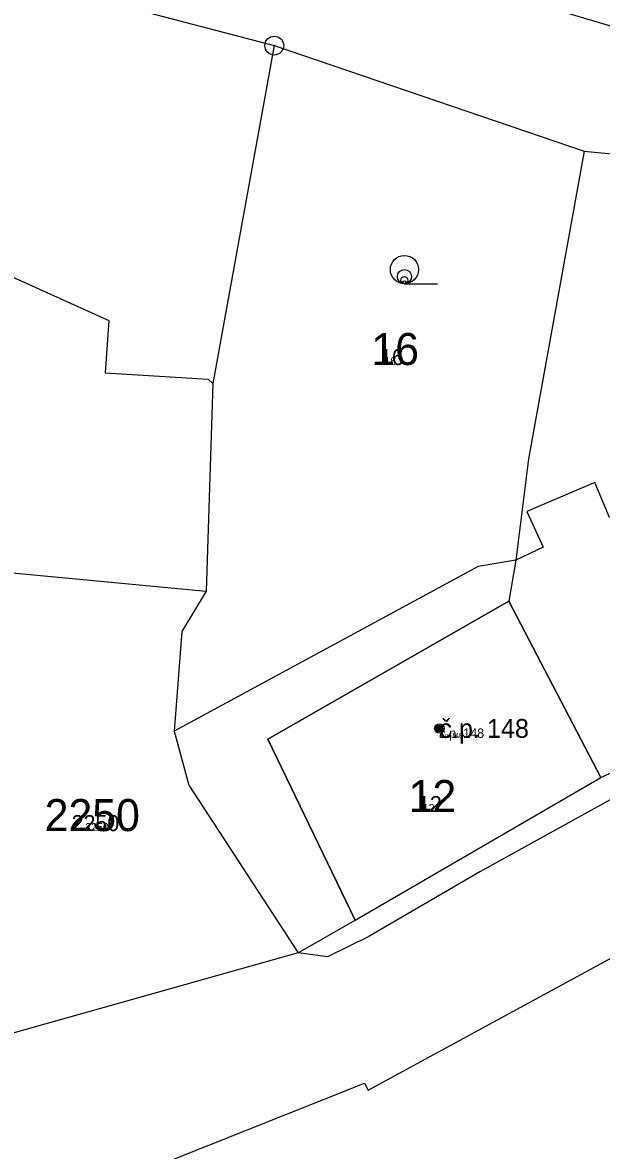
# Model space of a CAD drawing. Extents: x -744652 to -739090, y -980828 to -975855.
# Drawn here: x -742346.1 to -742315.3, y -978625.3 to -978565.5 of the extents above; entities that cross this region are included whole.
import ezdxf

# ---------------------------------------------------------------- set-up
doc = ezdxf.new("R2010")
doc.units = 0
for name, color, linetype in [('KAT_02_hranice parcel', 7, 'Continuous'), ('KAT_03_1000_st čísla parcelní', 7, 'Continuous'), ('KAT_03_1000_čísla parcelní', 7, 'Continuous'), ('KAT_03_1000_čísla popisná', 7, 'Continuous'), ('KAT_03_100_st čísla parcelní', 7, 'Continuous'), ('KAT_03_100_čísla parcelní', 7, 'Continuous'), ('KAT_03_100_čísla popisná', 7, 'Continuous'), ('KAT_03_250_st čísla parcelní', 7, 'Continuous'), ('KAT_03_250_čísla parcelní', 7, 'Continuous'), ('KAT_03_250_čísla popisná', 7, 'Continuous'), ('KAT_03_500_st čísla parcelní', 7, 'Continuous'), ('KAT_03_500_čísla parcelní', 7, 'Continuous'), ('KAT_03_500_čísla popisná', 7, 'Continuous'), ('KAT_04_vnitřní kresba', 7, 'Continuous'), ('KAT_05_1000_značky kultur', 7, 'Continuous'), ('KAT_05_100_značky kultur', 7, 'Continuous'), ('KAT_05_250_značky kultur', 7, 'Continuous'), ('KAT_05_500_značky kultur', 7, 'Continuous'), ('KAT_07_1000_značky budov', 7, 'Continuous'), ('KAT_07_100_značky budov', 7, 'Continuous'), ('KAT_07_500_značky budov', 7, 'Continuous'), ('KAT_11_značky bodu BP', 7, 'Continuous'), ('KAT_14_plocha_budovy', 7, 'Continuous')]:
    doc.layers.add(name, color=color, linetype=linetype)

msp = doc.modelspace()

# ---------------------------------------------------------------- linework, layer by layer
at = {"layer": 'KAT_02_hranice parcel'}
for p, q in [((-742355.44, -978560.72), (-742332.68, -978566.69)), ((-742332.68, -978566.69), (-742335.94, -978584.62)), ((-742332.68, -978566.69), (-742316.21, -978572.29)), ((-742335.94, -978584.62), (-742336.29, -978595.65)), ((-742315.33, -978605.55), (-742307.67, -978602)), ((-742331.41, -978614.86), (-742348.99, -978619.8))]:
    msp.add_line(p, q, dxfattribs=at)
for points in [[(-742307, -978567.97), (-742321.91, -978563.54), (-742327.66, -978561.91)], [(-742387.44, -978566.67), (-742378.28, -978570.02), (-742375.42, -978565.96), (-742341.47, -978581.28), (-742341.67, -978584.06), (-742336.19, -978584.39), (-742335.94, -978584.62)], [(-742316.21, -978572.29), (-742319.17, -978588.62), (-742319.85, -978594.01)], [(-742316.21, -978572.29), (-742310.83, -978572.81), (-742307.71, -978573.53)], [(-742310.03, -978589.56), (-742314.88, -978591.74), (-742315.66, -978589.88), (-742319.27, -978591.43), (-742318.4, -978593.32), (-742319.85, -978594.01)], [(-742387.49, -978613.33), (-742386.29, -978590.93), (-742336.29, -978595.65)], [(-742280.7, -978591.76), (-742280.38, -978592.84), (-742299.17, -978600.08), (-742308.59, -978603.78), (-742312.82, -978605.62), (-742321.76, -978610.55), (-742327.66, -978613.99), (-742329.86, -978615.06), (-742331.41, -978614.86)], [(-742319.85, -978594.01), (-742321.85, -978594.34), (-742337.99, -978603.09)], [(-742319.85, -978594.01), (-742320.22, -978596.19), (-742315.33, -978605.55)], [(-742336.29, -978595.65), (-742337.59, -978597.79), (-742337.99, -978603.09)], [(-742337.99, -978603.09), (-742337.22, -978605.96), (-742331.41, -978614.86)], [(-742331.41, -978614.86), (-742328.39, -978613.11), (-742315.33, -978605.55)], [(-742340.33, -978626.72), (-742327.89, -978621.78), (-742327.7, -978622.15), (-742311.7, -978613.45)]]:
    msp.add_lwpolyline(points, dxfattribs=at)
at = {"layer": 'KAT_03_1000_čísla popisná'}
msp.add_circle((-742323.91, -978602.94), 0.25, dxfattribs=at)
msp.add_circle((-742323.91, -978602.94), 0.25, dxfattribs=at)
at = {"layer": 'KAT_03_100_čísla popisná'}
msp.add_circle((-742323.91, -978602.94), 0.025, dxfattribs=at)
msp.add_circle((-742323.91, -978602.94), 0.025, dxfattribs=at)
at = {"layer": 'KAT_03_250_čísla popisná'}
msp.add_circle((-742323.91, -978602.94), 0.0625, dxfattribs=at)
msp.add_circle((-742323.91, -978602.94), 0.0625, dxfattribs=at)
at = {"layer": 'KAT_03_500_čísla popisná'}
msp.add_circle((-742323.91, -978602.94), 0.125, dxfattribs=at)
msp.add_circle((-742323.91, -978602.94), 0.125, dxfattribs=at)
at = {"layer": 'KAT_04_vnitřní kresba'}
for p, q in [((-742333.02, -978603.51), (-742320.22, -978596.19)), ((-742328.39, -978613.11), (-742333.02, -978603.51))]:
    msp.add_line(p, q, dxfattribs=at)
at = {"layer": 'KAT_05_1000_značky kultur'}
msp.add_line((-742325.763, -978579.33), (-742324.013, -978579.33), dxfattribs=at)
msp.add_circle((-742325.763, -978578.58), 0.75, dxfattribs=at)
at = {"layer": 'KAT_05_100_značky kultur'}
msp.add_line((-742325.769, -978579.33), (-742325.594, -978579.33), dxfattribs=at)
msp.add_circle((-742325.769, -978579.255), 0.075, dxfattribs=at)
at = {"layer": 'KAT_05_250_značky kultur'}
msp.add_line((-742325.768, -978579.33), (-742325.331, -978579.33), dxfattribs=at)
msp.add_circle((-742325.768, -978579.142), 0.187, dxfattribs=at)
at = {"layer": 'KAT_05_500_značky kultur'}
msp.add_line((-742325.767, -978579.33), (-742324.892, -978579.33), dxfattribs=at)
msp.add_circle((-742325.766, -978578.955), 0.375, dxfattribs=at)
at = {"layer": 'KAT_07_1000_značky budov'}
msp.add_circle((-742323.917, -978602.939), 0.175, dxfattribs=at)
at = {"layer": 'KAT_07_100_značky budov'}
msp.add_circle((-742323.911, -978602.94), 0.0175, dxfattribs=at)
at = {"layer": 'KAT_07_500_značky budov'}
for centre, radius in [((-742323.913, -978602.94), 0.0875), ((-742323.912, -978602.94), 0.0438)]:
    msp.add_circle(centre, radius, dxfattribs=at)
at = {"layer": 'KAT_11_značky bodu BP'}
for radius in [0.5, 0.0303]:
    msp.add_circle((-742332.68, -978566.69), radius, dxfattribs=at)
at = {"layer": 'KAT_14_plocha_budovy'}
for points in [[(-742319.85, -978594.01), (-742320.22, -978596.19), (-742315.33, -978605.55), (-742307.67, -978602), (-742309.88, -978594.57), (-742310.39, -978592.52), (-742310.03, -978589.56), (-742314.88, -978591.74), (-742315.66, -978589.88), (-742319.27, -978591.43), (-742318.4, -978593.32)], [(-742333.02, -978603.51), (-742328.39, -978613.11), (-742315.33, -978605.55), (-742320.22, -978596.19)]]:
    msp.add_lwpolyline(points, close=True, dxfattribs=at)

# ---------------------------------------------------------------- texts
at = {"layer": 'KAT_03_1000_st čísla parcelní'}
msp.add_text('12', height=1.7, dxfattribs=at).set_placement((-742325.542, -978607.38))
at = {"layer": 'KAT_03_1000_čísla parcelní'}
for s, p in [('16', (-742327.522, -978583.65)), ('2250', (-742344.877, -978608.39))]:
    msp.add_text(s, height=1.7, dxfattribs=at).set_placement(p)
at = {"layer": 'KAT_03_1000_čísla popisná'}
for s, height, p in [('č.p. 148', 1, (-742323.91, -978603.44)), ('12', 0.017, (-742324.561, -978607.38))]:
    msp.add_text(s, height=height, dxfattribs=at).set_placement(p)
at = {"layer": 'KAT_03_100_st čísla parcelní'}
msp.add_text('12', height=0.17, dxfattribs=at).set_placement((-742324.651, -978607.38))
at = {"layer": 'KAT_03_100_čísla parcelní'}
for s, p in [('16', (-742326.697, -978583.65)), ('2250', (-742342.299, -978608.39))]:
    msp.add_text(s, height=0.17, dxfattribs=at).set_placement(p)
at = {"layer": 'KAT_03_100_čísla popisná'}
for s, height, p in [('č.p. 148', 0.1, (-742323.91, -978603.44)), ('12', 0.0017, (-742324.553, -978607.38))]:
    msp.add_text(s, height=height, dxfattribs=at).set_placement(p)
at = {"layer": 'KAT_03_250_st čísla parcelní'}
msp.add_text('12', height=0.425, dxfattribs=at).set_placement((-742324.799, -978607.38))
at = {"layer": 'KAT_03_250_čísla parcelní'}
for s, p in [('16', (-742326.834, -978583.65)), ('2250', (-742342.729, -978608.39))]:
    msp.add_text(s, height=0.425, dxfattribs=at).set_placement(p)
at = {"layer": 'KAT_03_250_čísla popisná'}
for s, height, p in [('č.p. 148', 0.25, (-742323.91, -978603.44)), ('12', 0.00425, (-742324.554, -978607.38))]:
    msp.add_text(s, height=height, dxfattribs=at).set_placement(p)
at = {"layer": 'KAT_03_500_st čísla parcelní'}
msp.add_text('12', height=0.85, dxfattribs=at).set_placement((-742325.047, -978607.38))
at = {"layer": 'KAT_03_500_čísla parcelní'}
for s, p in [('16', (-742327.064, -978583.65)), ('2250', (-742343.445, -978608.39))]:
    msp.add_text(s, height=0.85, dxfattribs=at).set_placement(p)
at = {"layer": 'KAT_03_500_čísla popisná'}
for s, height, p in [('č.p. 148', 0.5, (-742323.91, -978603.44)), ('12', 0.0085, (-742324.556, -978607.38))]:
    msp.add_text(s, height=height, dxfattribs=at).set_placement(p)

doc.saveas('drawing.dxf')
